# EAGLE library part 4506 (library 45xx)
Dual expandable AND/OR/INVERT
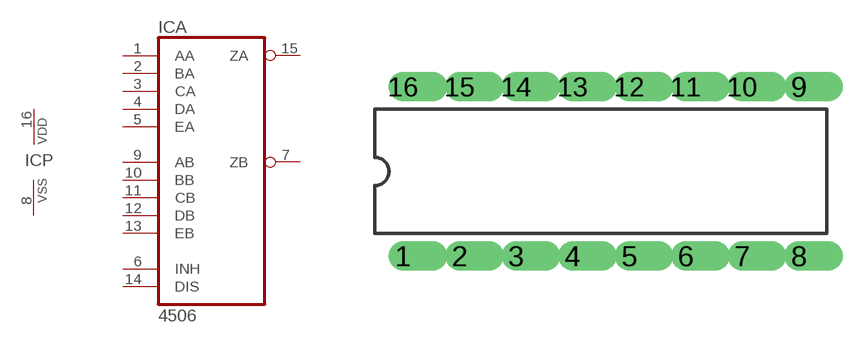
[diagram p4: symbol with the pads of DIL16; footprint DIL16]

Designator prefix IC; gates A=4506 P=PWRN

## 4506N  [DIL16]
1  A:AA  in
2  A:BA  in
3  A:CA  in
4  A:DA  in
5  A:EA  in
6  A:INH  in
7  A:ZB  out
8  P:VSS  pwr
9  A:AB  in
10  A:BB  in
11  A:CB  in
12  A:DB  in
13  A:EB  in
14  A:DIS  in
15  A:ZA  out
16  P:VDD  pwr

## Footprint DIL16 (pad centres in mm)
Dual In Line
drill 0.813 offset: 1 -8.89,-3.81; 2 -6.35,-3.81; 3 -3.81,-3.81; 4 -1.27,-3.81; 5 1.27,-3.81; 6 3.81,-3.81; 7 6.35,-3.81; 8 8.89,-3.81; 9 8.89,3.81; 10 6.35,3.81; 11 3.81,3.81; 12 1.27,3.81; 13 -1.27,3.81; 14 -3.81,3.81; 15 -6.35,3.81; 16 -8.89,3.81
